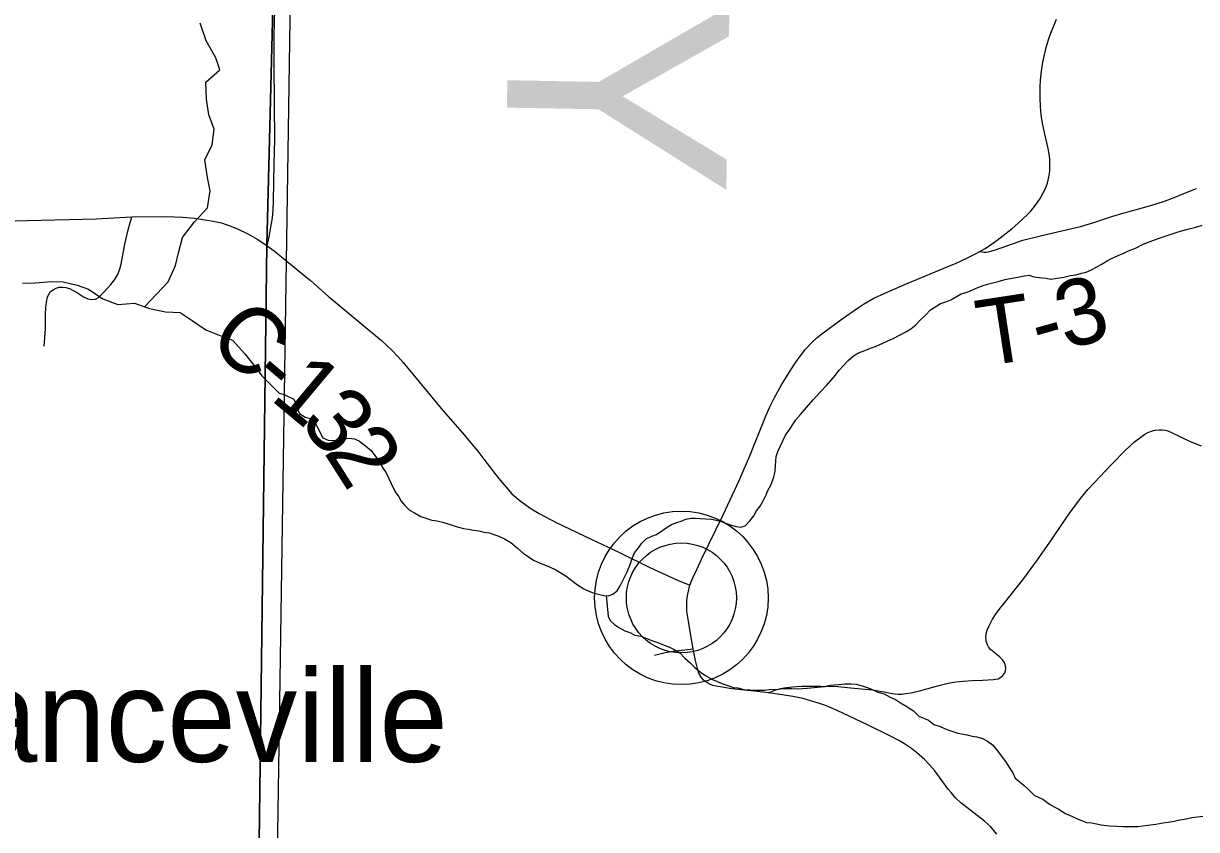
# Model space of a CAD drawing. Extents: x 0 to 34, y 0 to 22.
# Drawn here: x 26.826 to 27.832, y 17.051 to 17.742 of the extents above; entities that cross this region are included whole.
import ezdxf

# ---------------------------------------------------------------- set-up
doc = ezdxf.new("R2010")
doc.units = 0
for name, color, linetype in [('GM_X_Corporation', 7, 'Continuous'), ('GM_X_County', 7, 'Continuous'), ('GM_X_County_Road', 7, 'Continuous'), ('GM_X_County_Road_Text', 7, 'Continuous'), ('GM_X_County_Text', 7, 'Continuous'), ('GM_X_Minor_River', 7, 'Continuous'), ('GM_X_State_Route', 7, 'Continuous'), ('GM_X_Township_Road', 7, 'Continuous'), ('GM_X_Township_Road_Text', 7, 'Continuous'), ('GM_X_Unincorporated', 7, 'Continuous'), ('GM_X_Unincorporated_Location', 7, 'Continuous'), ('GM_X_Unincorporated_Text', 7, 'Continuous')]:
    doc.layers.add(name, color=color, linetype=linetype)

msp = doc.modelspace()

# ---------------------------------------------------------------- linework, layer by layer
at = {"layer": 'GM_X_Corporation'}
for points in [[(30.3167, 20.9), (27.1022, 20.9), (27.0898, 20.417), (27.0897, 20.4135), (27.089, 20.3692), (27.0873, 20.2665), (27.0907, 20.123), (27.0885, 20.1139), (27.0864, 20.0138), (27.0761, 19.6806), (27.0733, 19.498), (27.0719, 19.3912), (27.0487, 18.5805), (27.0419, 17.8236), (27.0349, 17.5522), (27.0234, 16.6611), (27.0124, 14.988), (27.0057, 14.5136), (27.2999, 14.5107), (27.8031, 14.5091), (28.4032, 14.497)], [(29.5503, 20.3788), (27.6751, 20.4106), (27.5829, 20.4116), (27.2336, 20.4152), (27.1239, 20.4163), (27.0898, 20.417), (27.0897, 20.4135), (27.089, 20.3692), (27.0873, 20.2665), (27.0907, 20.123), (27.0885, 20.1139), (27.0864, 20.0138), (27.0761, 19.6806), (27.0733, 19.498), (27.0719, 19.3912), (27.0487, 18.5805), (27.0419, 17.8236), (27.0349, 17.5522), (27.0234, 16.6611), (27.0124, 14.988), (27.0057, 14.5136), (27.2999, 14.5107), (27.8031, 14.5091), (28.4032, 14.497)], [(27.0234, 16.6611), (27.0349, 17.5522), (27.0419, 17.8236), (27.0487, 18.5805), (27.0719, 19.3912), (27.0733, 19.498), (27.0761, 19.6806), (27.0864, 20.0138), (27.0885, 20.1139), (27.0907, 20.123), (27.0873, 20.2665), (27.0031, 20.2673), (26.7822, 20.2704), (26.7196, 20.2707), (26.6351, 20.2734), (26.5702, 20.276), (26.2533, 20.2773), (25.4507, 20.2949), (24.5249, 20.3107), (24.0688, 20.3165), (24.0328, 20.3169), (23.5167, 20.3276), (23.5167, 14.5642)], [(27.0234, 16.6611), (27.0349, 17.5522), (27.0419, 17.8236), (27.0487, 18.5805), (27.0719, 19.3912), (27.0733, 19.498), (27.0761, 19.6806), (27.0864, 20.0138), (27.0885, 20.1139), (27.0907, 20.123), (27.0873, 20.2665), (27.0031, 20.2673), (26.7822, 20.2704), (26.7196, 20.2707), (26.6351, 20.2734), (26.5702, 20.276), (26.2533, 20.2773), (25.4507, 20.2949), (24.5249, 20.3107), (24.0688, 20.3165), (24.0328, 20.3169), (23.5167, 20.3276), (23.5167, 14.5642)]]:
    msp.add_lwpolyline(points, dxfattribs=at)
at = {"layer": 'GM_X_County'}
msp.add_line((27.1022, 20.9), (27.0057, 14.5136), dxfattribs=at)
at = {"layer": 'GM_X_County_Road'}
for points in [[(26.8085, 17.5727), (26.8297, 17.5731), (26.8887, 17.5747), (26.9191, 17.5763), (26.9486, 17.5766), (26.963, 17.5761), (26.973, 17.5751), (26.9818, 17.5737), (26.989, 17.5727), (26.996, 17.5711), (27.0032, 17.5686), (27.0099, 17.566), (27.0186, 17.5618), (27.0271, 17.5568), (27.0351, 17.5516)], [(27.0351, 17.5516), (27.0412, 17.5472), (27.0525, 17.5379), (27.0724, 17.5216), (27.0875, 17.5083), (27.1147, 17.4858), (27.1333, 17.4702), (27.142, 17.4623), (27.1474, 17.4565), (27.1519, 17.4514), (27.1726, 17.4266), (27.1846, 17.4119), (27.2041, 17.3893), (27.2168, 17.3741), (27.2212, 17.3685), (27.2288, 17.3584)], [(27.2288, 17.3584), (27.2303, 17.3565), (27.2366, 17.3486), (27.2419, 17.3424), (27.2452, 17.3388), (27.2522, 17.3327), (27.2561, 17.3297), (27.2606, 17.3266), (27.2643, 17.3243), (27.2685, 17.3219), (27.2838, 17.3139), (27.313, 17.2999), (27.3374, 17.2883), (27.3635, 17.2756), (27.3873, 17.2647), (27.3978, 17.2604)]]:
    msp.add_lwpolyline(points, dxfattribs=at)
at = {"layer": 'GM_X_Minor_River'}
for points in [[(26.93, 17.4992), (26.9402, 17.5099), (26.9503, 17.5206), (26.9566, 17.5347), (26.9591, 17.5454), (26.9627, 17.5587), (26.9728, 17.5721), (26.984, 17.584), (26.9864, 17.5988), (26.984, 17.6101), (26.9819, 17.6253), (26.9882, 17.6382), (26.9899, 17.6515), (26.9852, 17.664), (26.9832, 17.6772), (26.9826, 17.692), (26.9946, 17.7024), (26.9911, 17.7129), (26.9829, 17.7273), (26.9778, 17.7424)], [(27.4607, 17.3328), (27.4633, 17.3378), (27.4647, 17.3416), (27.4673, 17.3462), (27.4698, 17.3531), (27.4709, 17.358), (27.4712, 17.3626), (27.4718, 17.3706), (27.4732, 17.3751), (27.4798, 17.3889), (27.4835, 17.3943), (27.4861, 17.3981), (27.4883, 17.4019), (27.4927, 17.4069), (27.4979, 17.4127), (27.5035, 17.4193), (27.5094, 17.4258), (27.515, 17.4316), (27.5228, 17.4405), (27.5258, 17.4447), (27.5295, 17.4489), (27.5336, 17.4532), (27.538, 17.457), (27.5425, 17.4598), (27.5478, 17.4618), (27.5527, 17.4637), (27.5576, 17.4653), (27.5632, 17.4681), (27.567, 17.4697), (27.5722, 17.472), (27.5835, 17.4779), (27.5872, 17.4803), (27.5917, 17.4838), (27.5954, 17.4876), (27.5999, 17.4919), (27.6043, 17.4965), (27.6126, 17.5019), (27.6174, 17.5035), (27.6216, 17.5051), (27.6306, 17.5102), (27.6355, 17.5118), (27.6396, 17.5134), (27.6449, 17.5158), (27.6494, 17.5174), (27.6531, 17.5186), (27.6622, 17.521), (27.6671, 17.5222), (27.6708, 17.5231), (27.6791, 17.5247), (27.6848, 17.5256), (27.6889, 17.5264), (27.6928, 17.525), (27.6973, 17.5243), (27.703, 17.5236), (27.7075, 17.5229), (27.7128, 17.5238), (27.7185, 17.5247), (27.7241, 17.5259), (27.7287, 17.5267), (27.7336, 17.528), (27.7377, 17.5288), (27.7422, 17.5308), (27.7467, 17.5335), (27.7505, 17.5355), (27.7557, 17.5386), (27.7595, 17.5405), (27.7651, 17.5433), (27.77, 17.5453), (27.7741, 17.5473), (27.7801, 17.5496), (27.7865, 17.5528), (27.7902, 17.5544), (27.8004, 17.558), (27.8064, 17.56), (27.8166, 17.5635), (27.8218, 17.5648), (27.8271, 17.5664), (27.8316, 17.5676), (27.8373, 17.5692)], [(26.8255, 17.5194), (26.8361, 17.5196), (26.8505, 17.5209), (26.8603, 17.5206), (26.8724, 17.5177), (26.8819, 17.5144), (26.8942, 17.5059), (26.9071, 17.5011), (26.9214, 17.5024), (26.9343, 17.4977), (26.948, 17.4948), (26.9605, 17.4942), (26.9708, 17.4875), (26.9826, 17.4793), (26.9955, 17.4742), (27.0054, 17.4705), (27.0161, 17.4589), (27.0257, 17.4465), (27.0306, 17.4398)], [(27.0306, 17.4398), (27.0455, 17.4252), (27.0497, 17.4238), (27.0539, 17.422), (27.0577, 17.4201), (27.0601, 17.416), (27.0609, 17.4122), (27.0629, 17.4077), (27.0679, 17.4044), (27.0724, 17.4033), (27.0763, 17.3992), (27.079, 17.3947), (27.0806, 17.391), (27.0829, 17.3868), (27.0875, 17.3846), (27.0932, 17.3844), (27.0977, 17.3856), (27.1056, 17.3865), (27.1102, 17.3858), (27.1144, 17.384), (27.1197, 17.3799), (27.1244, 17.3758), (27.1306, 17.3672), (27.1348, 17.3605), (27.1372, 17.3567), (27.1415, 17.3477), (27.145, 17.3405), (27.1481, 17.3361), (27.1501, 17.3323), (27.1532, 17.3286), (27.1574, 17.3248), (27.1616, 17.3223), (27.167, 17.3193), (27.1765, 17.3161), (27.181, 17.3154), (27.1856, 17.3143), (27.1905, 17.3129), (27.1947, 17.3115), (27.1993, 17.31), (27.2035, 17.309), (27.208, 17.3083), (27.2122, 17.3076), (27.2167, 17.3069), (27.2213, 17.3059), (27.2259, 17.3052), (27.2297, 17.3037), (27.2339, 17.3023), (27.2388, 17.3001), (27.2442, 17.2968), (27.2499, 17.292), (27.2549, 17.2879), (27.2603, 17.2842), (27.2641, 17.2816), (27.2687, 17.2794), (27.2736, 17.2776), (27.2774, 17.2762), (27.2828, 17.2736), (27.287, 17.271), (27.2916, 17.2681), (27.3015, 17.2607), (27.3069, 17.2573), (27.3111, 17.2551), (27.3149, 17.2537), (27.324, 17.2516), (27.3278, 17.2513), (27.3316, 17.2525), (27.3353, 17.2556), (27.3379, 17.2598), (27.3405, 17.2648), (27.3437, 17.2713), (27.3467, 17.2781), (27.3481, 17.2823), (27.3503, 17.2881), (27.3536, 17.2923), (27.3565, 17.2965), (27.3603, 17.3), (27.3652, 17.3023), (27.3693, 17.3039), (27.3745, 17.3074), (27.3783, 17.3102), (27.382, 17.3125), (27.3865, 17.3141), (27.3903, 17.3153), (27.3944, 17.3169), (27.3989, 17.3177), (27.4027, 17.3178), (27.4065, 17.3175), (27.4111, 17.3172), (27.4164, 17.3169), (27.4202, 17.3162), (27.424, 17.3151), (27.4278, 17.3137), (27.4323, 17.3122), (27.4377, 17.3108), (27.4415, 17.3101), (27.4452, 17.3113), (27.4493, 17.3156), (27.4526, 17.3198), (27.4548, 17.324), (27.4582, 17.3282), (27.4607, 17.3328)], [(27.3259, 17.2514), (27.3277, 17.2338), (27.3293, 17.2301), (27.3332, 17.2267), (27.3374, 17.2238), (27.342, 17.2212), (27.3462, 17.2197), (27.3507, 17.2175), (27.3557, 17.2165), (27.3595, 17.2151), (27.3644, 17.2132), (27.3686, 17.2118), (27.3728, 17.21), (27.3804, 17.2071), (27.3842, 17.2052), (27.3892, 17.2023), (27.3935, 17.1978), (27.3981, 17.1937), (27.4019, 17.1896), (27.4069, 17.1856), (27.4107, 17.183), (27.4172, 17.1793), (27.426, 17.1757), (27.4302, 17.1742), (27.4348, 17.1724), (27.4389, 17.1721), (27.4442, 17.1707), (27.4492, 17.1704), (27.453, 17.1701), (27.462, 17.1702), (27.4658, 17.1707), (27.4738, 17.1712), (27.4779, 17.1716), (27.4851, 17.1718), (27.4904, 17.1715), (27.4983, 17.172), (27.5134, 17.1734), (27.518, 17.1746), (27.5255, 17.1751), (27.5304, 17.1756), (27.5357, 17.1757), (27.5403, 17.1754), (27.5456, 17.174), (27.5498, 17.1725), (27.5536, 17.1711), (27.5589, 17.1685), (27.5643, 17.1671), (27.5696, 17.1642), (27.5742, 17.1623), (27.5784, 17.1594), (27.5834, 17.1564), (27.5895, 17.1524), (27.5941, 17.1479), (27.6025, 17.1446), (27.6071, 17.1409), (27.6124, 17.1391), (27.6181, 17.1366), (27.6277, 17.1333), (27.6356, 17.132), (27.6398, 17.1309), (27.644, 17.1302), (27.6489, 17.1288), (27.6531, 17.1266), (27.6573, 17.1232), (27.6604, 17.1195), (27.6686, 17.109), (27.6713, 17.1045), (27.6748, 17.0993), (27.6768, 17.0948), (27.6844, 17.0885), (27.6883, 17.0851), (27.6933, 17.0799), (27.7005, 17.0766), (27.7063, 17.0725), (27.7101, 17.07), (27.7143, 17.0681), (27.7197, 17.0644), (27.7235, 17.063), (27.7303, 17.0597), (27.738, 17.0568), (27.7425, 17.0565), (27.7505, 17.0548), (27.7577, 17.0537), (27.7641, 17.0535), (27.7694, 17.0532), (27.7819, 17.0534), (27.7906, 17.0543), (27.7974, 17.0552), (27.8038, 17.0564), (27.808, 17.0569), (27.8132, 17.0578), (27.8181, 17.059), (27.8234, 17.0598), (27.8283, 17.0611), (27.8378, 17.062)]]:
    msp.add_lwpolyline(points, dxfattribs=at)
at = {"layer": 'GM_X_State_Route'}
msp.add_line((27.4652, 17.168), (27.4554, 17.1691), dxfattribs=at)
for points in [[(27.6465, 17.5466), (27.651, 17.5492), (27.6556, 17.5523), (27.6613, 17.5564), (27.6741, 17.5664), (27.679, 17.5707), (27.6873, 17.5783), (27.6901, 17.5813), (27.6942, 17.5863), (27.6957, 17.5883), (27.6983, 17.5921), (27.7006, 17.5965), (27.7027, 17.6008), (27.7044, 17.6052), (27.7057, 17.6103), (27.7064, 17.6154), (27.7066, 17.62), (27.7064, 17.626), (27.7059, 17.6301), (27.705, 17.6351), (27.7019, 17.6488), (27.7003, 17.6567), (27.6992, 17.6639), (27.6985, 17.6706), (27.6981, 17.6787), (27.6983, 17.6878), (27.6986, 17.6937), (27.6994, 17.7012), (27.7006, 17.7092), (27.7019, 17.7154), (27.7035, 17.7217), (27.7058, 17.7293), (27.708, 17.7354), (27.7122, 17.7459)], [(27.5828, 17.5185), (27.6186, 17.5335), (27.6263, 17.5367), (27.6353, 17.5408), (27.6421, 17.5442), (27.6465, 17.5466)], [(27.3978, 17.2604), (27.401, 17.2681), (27.4026, 17.2713), (27.4079, 17.2827), (27.4262, 17.3206), (27.4401, 17.3502), (27.4436, 17.3581), (27.4492, 17.3712), (27.462, 17.4032), (27.4633, 17.4063), (27.4665, 17.4134), (27.4704, 17.4214), (27.4764, 17.4323), (27.4829, 17.4428), (27.4875, 17.45), (27.4915, 17.4557), (27.4937, 17.4586), (27.4968, 17.4624), (27.5031, 17.4692), (27.5071, 17.4728), (27.5111, 17.4761), (27.5285, 17.4887), (27.5424, 17.4987), (27.5468, 17.5015), (27.5557, 17.5066), (27.5645, 17.5107), (27.5828, 17.5185)], [(27.4554, 17.1691), (27.4525, 17.1694), (27.4337, 17.1715), (27.4202, 17.1736), (27.4174, 17.1743), (27.4145, 17.1754), (27.4128, 17.1764), (27.4095, 17.1789), (27.4071, 17.1821), (27.4056, 17.1847), (27.4042, 17.1889), (27.4027, 17.1957), (27.4007, 17.2058), (27.3981, 17.2205), (27.396, 17.233), (27.3953, 17.2379), (27.3951, 17.243), (27.3952, 17.2478), (27.3959, 17.2526), (27.3971, 17.2578), (27.3978, 17.2604)], [(27.6612, 17.0467), (27.6555, 17.0532), (27.6504, 17.0577), (27.6327, 17.0715), (27.6301, 17.0737), (27.6259, 17.0777), (27.6218, 17.0823), (27.6193, 17.0854), (27.6078, 17.101), (27.6037, 17.1058), (27.5989, 17.1108), (27.5923, 17.1167), (27.5879, 17.1201), (27.5818, 17.1243), (27.5776, 17.1268), (27.5693, 17.1311), (27.5506, 17.1403), (27.524, 17.1528), (27.5176, 17.1556), (27.5133, 17.1573), (27.509, 17.1589), (27.5024, 17.1609), (27.4948, 17.163), (27.4861, 17.1647), (27.477, 17.1663), (27.4652, 17.168)]]:
    msp.add_lwpolyline(points, dxfattribs=at)
at = {"layer": 'GM_X_Township_Road'}
for points in [[(27.0351, 17.5516), (27.0372, 17.5602), (27.0375, 17.5627), (27.0399, 17.5754), (27.0405, 17.5819), (27.0408, 17.5902), (27.0411, 17.6218), (27.0417, 17.643), (27.0415, 17.6722), (27.0411, 17.7088), (27.0412, 17.7318), (27.0418, 17.7548)], [(27.6465, 17.5466), (27.6498, 17.5461), (27.6517, 17.546), (27.6537, 17.5462), (27.6567, 17.5471), (27.6599, 17.548), (27.6835, 17.5564), (27.6973, 17.5599), (27.7095, 17.5625), (27.7206, 17.5651), (27.7329, 17.5682), (27.7443, 17.5716), (27.752, 17.5741), (27.7605, 17.5768), (27.7683, 17.5791), (27.7849, 17.5839), (27.7941, 17.5864), (27.8041, 17.5895), (27.8104, 17.5919), (27.8244, 17.5976), (27.8324, 17.6007)], [(26.844, 17.4654), (26.845, 17.4804), (26.8452, 17.4927), (26.8453, 17.4986), (26.8459, 17.5031), (26.8469, 17.5076), (26.8479, 17.5098), (26.8495, 17.5123), (26.8516, 17.5137), (26.8544, 17.5152), (26.8569, 17.5159), (26.8601, 17.516), (26.8626, 17.5157), (26.8658, 17.5148), (26.8683, 17.5135), (26.8716, 17.5116), (26.8776, 17.5077), (26.8813, 17.506), (26.8848, 17.5053), (26.888, 17.5058), (26.8906, 17.5071), (26.8952, 17.5117), (26.9012, 17.5182), (26.9043, 17.5224), (26.9073, 17.527), (26.909, 17.5316), (26.9101, 17.5358), (26.9133, 17.5528), (26.9157, 17.5642), (26.9175, 17.5703), (26.9182, 17.5733), (26.9191, 17.5763)], [(27.4652, 17.168), (27.4707, 17.1702), (27.4747, 17.1715), (27.4783, 17.1723), (27.4857, 17.1732), (27.4935, 17.1737), (27.5003, 17.1738), (27.51, 17.1737), (27.5248, 17.1733), (27.5388, 17.172), (27.5545, 17.1704), (27.5644, 17.1687), (27.57, 17.1676), (27.5733, 17.1671), (27.5764, 17.1669), (27.5793, 17.1669), (27.5826, 17.1673), (27.5875, 17.168), (27.5959, 17.17), (27.6113, 17.1742), (27.6169, 17.1757), (27.6208, 17.1765), (27.626, 17.1773), (27.6323, 17.178), (27.6398, 17.1785), (27.6487, 17.1789), (27.6581, 17.1794), (27.6602, 17.1796), (27.6621, 17.1801), (27.6644, 17.1814), (27.6662, 17.1828), (27.6679, 17.185), (27.6685, 17.1869), (27.6688, 17.1892), (27.6683, 17.1924), (27.6674, 17.1943), (27.6659, 17.1963), (27.6633, 17.1989), (27.6584, 17.2027), (27.6556, 17.2051), (27.6539, 17.2074), (27.653, 17.2091), (27.652, 17.2121), (27.6518, 17.2133), (27.6516, 17.2155), (27.6518, 17.2186), (27.6527, 17.2216), (27.6544, 17.2255), (27.6574, 17.2312), (27.66, 17.2353), (27.6638, 17.2405), (27.6668, 17.2441), (27.6841, 17.2661), (27.6959, 17.2822), (27.7085, 17.3), (27.7174, 17.3133), (27.7236, 17.3223), (27.7327, 17.3347), (27.7392, 17.3423), (27.7445, 17.348), (27.7592, 17.3637), (27.7713, 17.3762), (27.7792, 17.3834), (27.7826, 17.386), (27.7858, 17.3882), (27.7879, 17.3898), (27.7901, 17.391), (27.7929, 17.3923), (27.7953, 17.393), (27.797, 17.3934), (27.8004, 17.3937), (27.8028, 17.3936), (27.8055, 17.3932), (27.8076, 17.3927), (27.8103, 17.3916), (27.827, 17.3837), (27.8362, 17.3799)], [(27.3675, 17.2002), (27.3767, 17.2025), (27.3853, 17.2039), (27.3935, 17.2049), (27.4007, 17.2058)]]:
    msp.add_lwpolyline(points, dxfattribs=at)
at = {"layer": 'GM_X_Unincorporated'}
for radius in [0.0744, 0.0472]:
    msp.add_circle((27.3905, 17.2494), radius, dxfattribs=at)
at = {"layer": 'GM_X_Unincorporated_Location'}
msp.add_line((27.3905, 17.2494), (27.3905, 17.2494), dxfattribs=at)

# ---------------------------------------------------------------- texts
at = {"layer": 'GM_X_County_Road_Text'}
for s, rotation, p in [('C', 317.4404, (26.9824, 17.4689)), ('-', 319.682, (27.0186, 17.4358)), ('1', 320.1295, (27.0367, 17.4204)), ('3', 310.2976, (27.0618, 17.3997)), ('2', 302.4516, (27.0832, 17.3747))]:
    msp.add_text(s, height=0.0568, rotation=rotation, dxfattribs=at).set_placement(p)
at = {"layer": 'GM_X_County_Text'}
msp.add_text('BELMONT COUNTY', height=0.189394, rotation=268.998, dxfattribs=at).set_placement((27.2809, 19.9608))
at = {"layer": 'GM_X_Township_Road_Text'}
for s, rotation, p in [('3', 15.3035, (27.7202, 17.4622)), ('T', 8.7204, (27.6485, 17.4478)), ('-', 15.7151, (27.6979, 17.4559))]:
    msp.add_text(s, height=0.0568, rotation=rotation, dxfattribs=at).set_placement(p)
at = {"layer": 'GM_X_Unincorporated_Text'}
msp.add_text('Temperanceville', height=0.078977, rotation=0, dxfattribs=at).set_placement((26.4154, 17.1087))

doc.saveas('drawing.dxf')
